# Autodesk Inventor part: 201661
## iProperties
Created: 2007-12
Part Number: 201661
Document SubType Name: Modeling
Designer: MM
Density: 7.85 g/cm^3
Mass: 262.658 g
Surface Area: 247.482 cm^2
Volume: 33.4596 cm^3
Description: BACK SUPPORT PLATE
Material: Steel
Component Category: Lower Component
Author: MM
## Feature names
1. TaggingFeature2
